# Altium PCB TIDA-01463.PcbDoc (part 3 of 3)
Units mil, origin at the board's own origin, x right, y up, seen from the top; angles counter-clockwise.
Board outline 6100 x 1060 mil, 4 copper layers (Top Layer, Signal Layer 1, Signal Layer 2, Bottom Layer), stack 61.2 mil thick; 209 components, 128 nets, 660 pads, 266 vias.
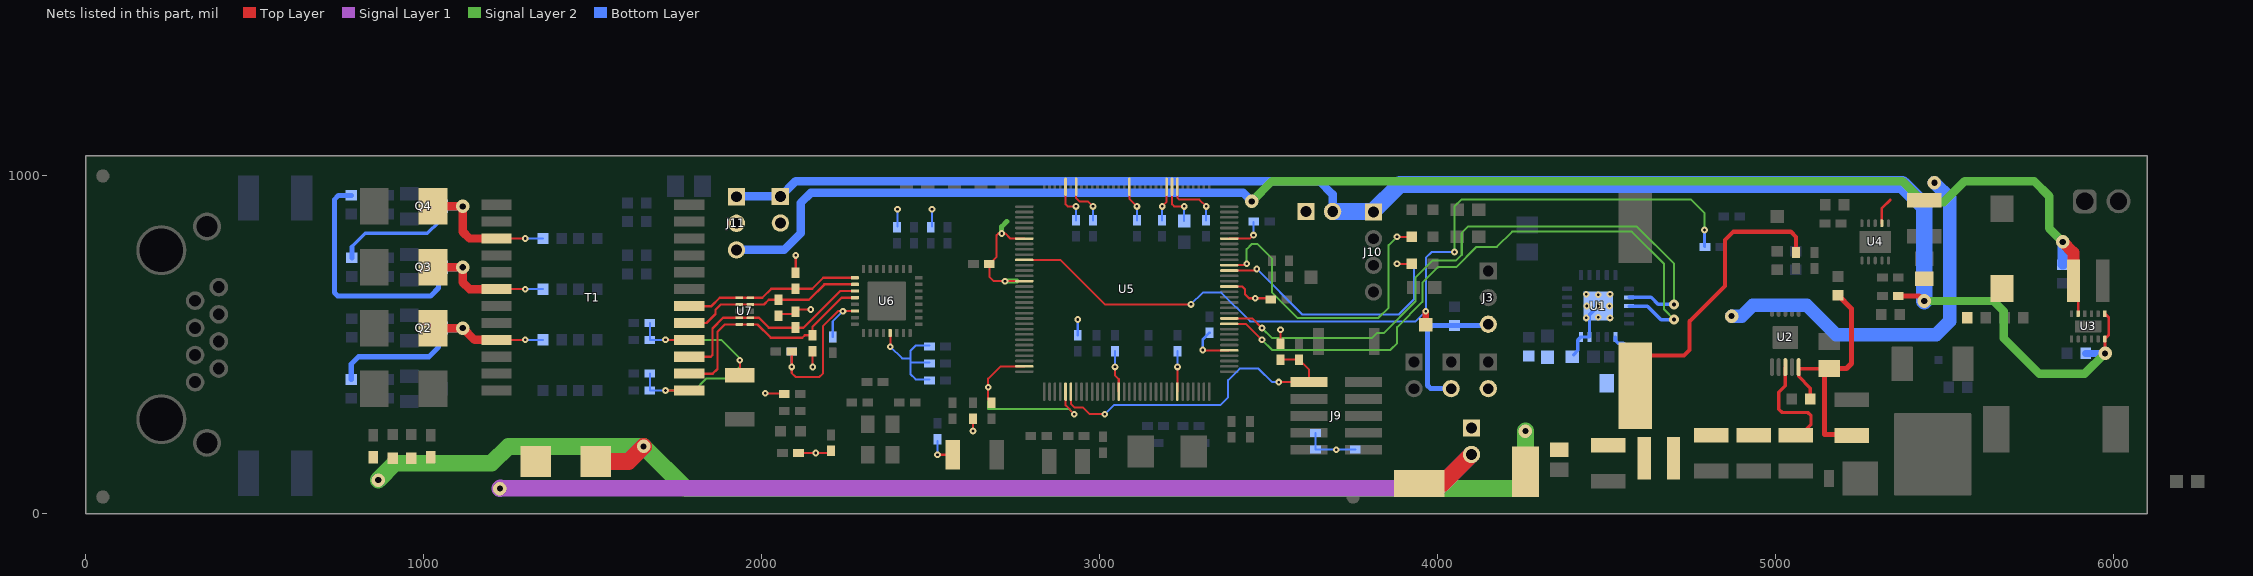
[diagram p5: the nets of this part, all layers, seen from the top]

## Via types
v1: diameter 20, hole 8, Top Layer to Bottom Layer, 184 vias
v2: diameter 40, hole 18, Top Layer to Bottom Layer, 50 vias
v3: diameter 19.68, hole 7.87, Top Layer to Bottom Layer, 21 vias
v4: diameter 30, hole 12, Top Layer to Bottom Layer, 11 vias

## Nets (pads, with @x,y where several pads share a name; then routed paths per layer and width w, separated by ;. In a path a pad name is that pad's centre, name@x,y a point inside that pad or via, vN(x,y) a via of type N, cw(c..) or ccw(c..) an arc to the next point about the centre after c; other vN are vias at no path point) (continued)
PR36: C7.1 D2.2 Q2.3 R9.2 T1.21 | length 793.1
  Top Layer w6: T1.21@1214.96,515 v1(1300,515)
  Top Layer w25: D2.2@1027.01,550 v2(1115,550) 1150,515 T1.21@1214.96,515
  Bottom Layer w6: v1(1300,515) C7.1@1352.44,515
  Bottom Layer w15: R9.2@785,397.56 785,443.35 806.65,465 1015,465 1043.31,493.31 Q2.3@1043.31,550
  Bottom Layer w25: Q2.3@1043.31,550 v2(1115,550)
PR45: C8.1 D3.2 Q3.3 R12.2 T1.18 | length 1164.4
  Top Layer w6: T1.18@1214.96,665 v1(1300,665)
  Top Layer w25: D3.2@1027.01,730 v2(1115,730) 1115,685 1135,665 T1.18@1214.96,665
  Bottom Layer w6: v1(1300,665) C8.1@1352.44,665
  Bottom Layer w15: R12.2@785,942.56 747.56,942.56 735,930 735,655 745,645 1020,645 1043.31,668.31 Q3.3@1043.31,730
  Bottom Layer w25: Q3.3@1043.31,730 v2(1115,730)
PR78: C9.1 D4.2 Q4.3 R11.2 T1.15 | length 845.6
  Top Layer w6: T1.15@1214.96,815 v1(1300,815)
  Top Layer w25: D4.2@1027.01,910 v2(1115,910) 1115,835 1135,815 T1.15@1214.96,815
  Bottom Layer w6: v1(1300,815) C9.1@1352.44,815
  Bottom Layer w10: 786.69,790.19 826.5,830 1010,830 1045,865 Q4.3@1045,908.31
  Bottom Layer w15: R11.2@786.69,757.56 786.69,790.19
  Bottom Layer w25: Q4.3@1043.31,910 v2(1115,910)
PWM_DIM: R69.1 TP5.1 U5.43 | length 2595
  Top Layer w6: U5.43@2776.85,751.61 2883.39,751.61 3015,620 v1(3270,620)
  Top Layer w20: TP5.1@3965,560 v1(3965,600)
  Signal Layer 2 w6: v1(4050,775) 4050,910 4070,930 4750,930 4790,890 v1(4790,840)
  Bottom Layer w6: v1(3270,620) 3305,655 3360,655 3445,570 3935,570 v1(3965,600) 3965,757.54 3982.46,775 v1(4050,775) ; R69.1@4790,791.38 R69.1@4791.38,790
  Bottom Layer w8: R69.1@4790,791.38 v1(4790,840)
RST_N: C54.1 J9.10 R47.1 R48.2 U5.70 | length 1051.8
  Top Layer w6: U5.70@2914.65,361.85 2914.65,325.35 2925,315 2950,315 2970,295 v1(3015,295) ; v1(3530,390) J9.10@3619.88,390 3619.88,426.5 R48.2@3590,456.38 R47.1@3535,456.38
  Bottom Layer w6: v1(3015,295) 3041.65,321.65 3356.65,321.65 3380,345 3380,395.91 3414.09,430 3470,430 3510,390 v1(3530,390) C54.1@3591.38,390
RXD_N: R55.1 T1.6 U6.9 U7.1 U7.10 | length 525.2
  Top Layer w7: T1.6@1785.04,615 1851,615 1875.37,639.37 U7.1@1933.56,639.37 U7.10@1966.44,639.37 2001.37,639.37 2028.38,666.38 R55.1@2100,666.38 2149.38,666.38 2181.9,698.9 U6.9@2275.51,698.9
RXD_P: R54.1 T1.5 U6.10 U7.2 U7.9 | length 545
  Top Layer w7: T1.5@1785.04,565 1836.4,565 1863,591.6 1863,604 1878.69,619.69 U7.2@1933.56,619.69 U7.9@1966.44,619.69 2006.69,619.69 2020.62,633.62 R54.1@2050,633.62 2139.62,633.62 2185.21,679.21 U6.10@2275.51,679.21
TPH: U1.18 U5.106 | length 1892
  Top Layer w6: U5.106@3383.15,562.64 3432.36,562.64 v1(3480,515)
  Signal Layer 2 w6: v1(3480,515) 3510,485 3860,485 3880,505 3880,552.7 3955,627.7 3955,684.57 4000.43,730 4055,730 4115,790 4175.29,790 4220.29,835 4575,835 4670,740 4670,605 v4(4700,575)
  Bottom Layer w10: U1.18@4566.54,615 4621.05,615 4661.05,575 v4(4700,575)
TPH_LED: D6.2 U5.116 | length 813.1
  Top Layer w6: U5.116@3383.15,720.12 3460.12,720.12 v1(3465,725) ; v1(3880,740) D6.2@3923.5,740
  Bottom Layer w6: v1(3465,725) 3600,590 3885,590 3930,635 3930,725 3915,740 v1(3880,740)
TPL: U1.17 U5.107 | length 1864.7
  Top Layer w6: U5.107@3383.15,578.39 3451.61,578.39 v1(3480,550)
  Signal Layer 2 w6: v1(3480,550) 3510,520 3805,520 3820,535 3840,535 3935,630 3935,700 3985,750 4055,750 4071.4,766.4 4071.4,831.91 4089.49,850 4590.01,850 4700,740.01 v4(4700,620)
  Bottom Layer w10: U1.17@4566.54,640.59 4631.51,640.59 4652.1,620 v4(4700,620)
TPL_LED: D7.2 U5.117 | length 948.7
  Top Layer w6: U5.117@3383.15,735.87 3430.87,735.87 v1(3435,740) ; v1(3880,820) D7.2@3923.5,820
  Signal Layer 2 w6: v1(3435,740) 3435,783.11 3450.75,798.86 3466.14,798.86 3510,755 3510,655 3585,580 3825,580 3855,610 3855,795 v1(3880,820)
TXD_N: R53.1 T1.3 U6.11 U7.4 U7.7 | length 641.6
  Top Layer w7: T1.3@1785.04,465 1849,465 1854,470 1854,549 1885.32,580.32 U7.4@1933.56,580.32 U7.7@1966.44,580.32 1991.68,580.32 2021,551 2123.57,551 2232.1,659.53 U6.11@2275.51,659.53
TXD_P: R52.1 T1.2 U6.12 U7.5 U7.6 | length 695.7
  Top Layer w7: T1.2@1785.04,415 1855,415 1869,429 1869,539 1890.63,560.63 U7.5@1933.56,560.63 U7.6@1966.44,560.63 1987.37,560.63 2027,521 2120,521 2127.62,528.62 R52.1@2150,528.62 2150,554 2235.84,639.84 U6.12@2275.51,639.84
VCC_1P8: C29.1 J11.3 L5.2 U3.5 | length 4564.1
  Top Layer w8: L5.2@5881.69,690 5895.47,676.22 U3.5@5895.47,592.4
  Top Layer w35: v2(5850,805) 5881.69,773.31 L5.2@5881.69,690
  Signal Layer 2 w25: v2(3450,925) 3510,985 5375,985 5437.76,922.24 5497.24,922.24 5560,985 5765,985 5810,940 5810,845 v2(5850,805)
  Bottom Layer w25: J11.3@1925,781.26 2066.26,781.26 2115,830 2115,920 2145.5,950.5 3395,950 3425,950 v2(3450,925)
  Bottom Layer w30: C29.1@5850,737.56 v2(5850,805)
VCC_3P3: C57.1 C58.1 C59.1 C60.1 J12.2 R57.1 R58.2 R60.2 R61.2 R64.1 R65.2 R66.2 U6.21 | length 770.9
  Top Layer w6: v1(2010,356.81) R66.2@2066.38,356.81 ; R64.1@2108.62,180 v1(2160,180) 2198.62,180 R58.2@2205,186.38 ; v1@2380.32,495.12 U6.21@2380.32,540.47 ; v1(2520,175) C57.1@2565.04,175 C57.1@2565.04,175 C57.1@2565.04,155 ; v1(2625,245) R61.2@2625,281.38
  Bottom Layer w6: v1(2380.47,494.96) 2415.43,460 2440,460 ; R60.2@2401.81,850.43 v1(2401.81,901.81) ; C59.1@2496.38,398.35 2455,398.35 2440,413.35 2440,448.35 ; C60.1@2496.38,448.35 2440,448.35 ; C58.1@2496.38,498.35 2455,498.35 2440,483.35 2440,460 ; R65.2@2503.62,850.43 v1(2503.62,901.81) ; v1(2520,175) R57.1@2520,215.47 ; 2440,448.35 2440,460
VCC_3P3_EXT: C27.1 C28.1 C30.1 J8.2 J10.1 J11.1 J12.1 L6.2 R34.2 U3.1 U3.12 | length 4903.6
  Top Layer w8: U3.1@5974.21,592.4 5986.02,580.59 5986.02,529.41 U3.12@5974.21,517.6 5975,516.81 v2(5975,475)
  Top Layer w15: R34.2@5363.62,645 5425,645 v2(5440,630)
  Signal Layer 2 w25: v2(5440,630) 5645,630 5675,600 5675,520 5780,415 5915,415 v2(5975,475)
  Bottom Layer w20: C28.1@5917.56,475 v2(5975,475)
  Bottom Layer w25: J11.1@1925.63,939.37 J12.1@2055,939.37 2100.63,985 3650,985 3689.37,945.63 J8.2@3689.37,895
  Bottom Layer w50: J8.2@3689.37,895 3808.11,895 3888.11,975 5375,975 5440,910 v2(5440,630)
VCC_3P3_M: C34.1 C35.1 C36.1 C37.1 C38.1 C39.1 C40.1 C41.1 C42.1 C43.1 C44.1 C45.1 C46.1 J8.1 R41.2 R42.2 R43.2 R46.1 R47.2 U5.7 U5.8 U5.9 U5.16 U5.26 U5.28 U5.39 U5.47 U5.63 U5.69 U5.79 U5.90 U5.101 U5.113 U5.122 | length 2689.3
  Top Layer w6: C43.1@2680,328.62 2670,338.62 v1(2670,375) 2670,400 2706.65,436.65 U5.63@2776.85,436.65 ; U5.47@2776.85,688.62 v1(2720,688.62) 2686.38,688.62 2673.62,701.38 C44.1@2673.62,740 2695,761.38 2695,825 2700,830 v1(2710,830) 2720,830 2735,815 2776.46,815 U5.39@2776.85,814.61 ; U5.69@2898.9,361.85 2898.9,321.1 v1(2925,295) ; U5.28@2898.9,968.15 2898.9,916.1 2905,910 v1(2930,910) ; U5.26@2930.39,968.15 2930.39,934.61 2940,925 2965,925 v1(2980,910) ; v1(3045,435) 3045,410 3056.38,398.62 U5.79@3056.38,361.85 ; U5.16@3087.87,968.15 3087.87,932.13 v1(3110,910) ; v1(3185,910) 3198.11,923.11 U5.9@3198.11,968.15 ; U5.8@3213.86,968.15 3213.86,916.14 3220,910 v1(3250,910) ; U5.90@3229.61,361.85 3229.61,434.61 v1(3230,435) ; U5.7@3229.61,968.15 3229.61,935.39 3235,930 3295,930 v1(3315,910) ; v1(3305,485) 3306.1,483.9 U5.101@3383.15,483.9 ; U5.113@3383.15,672.87 3422.13,672.87 3430,665 3430,650 3441.85,638.15 v1(3460,638.15) C42.1@3508.23,638.15 ; U5.122@3383.15,814.61 3444.61,814.61 v1(3455,825) ; R47.2@3535,503.63 v1(3535,545)
  Signal Layer 2 w6: v1(2670,375) 2670,310 2910,310 v1(2925,295)
  Signal Layer 2 w15: v1(2710,830) 2710,850 2725,865 ; v1(2720,688.62) 2755,688.62
  Bottom Layer w6: C38.1@2930,868.62 v1(2930,910) ; R46.1@2935,528.62 v1(2935,575) ; C37.1@2980,868.62 v1(2980,910) ; v1(3045,435) C39.1@3045,481.38 ; C36.1@3110,868.62 v1(3110,910) ; C34.1@3185,868.62 v1(3185,910) ; v1(3230,435) C40.1@3230,481.38 ; C35.1@3250,866.5 v1(3250,910) ; C46.1@3315,868.62 v1(3315,910) ; v1(3455,825) C45.1@3455,863.62 ; R42.2@3638.62,240 R41.2@3638.62,190 v1(3700,190) R43.2@3756.38,190
  Bottom Layer w8: v1(3305,485) 3305,516.38 C41.1@3325,536.38
VCC_SW: C1.1 C2.1 C3.1 C4.1 C61.1 C62.1 C63.1 C64.1 J11.2 R52.2 R53.2 R54.2 R55.2 T1.1 T1.4 U6.14 | length 1625.2
  Top Layer w6: v1@1710,365 T1.1@1785.04,365 ; v1(1715,515) T1.4@1785.04,515 ; C61.1@1935,409.96 v1(1935,455) ; R54.2@2050.47,591.34 2089.45,591.34 2103.11,605 v1(2145,605) ; C64.1@2088.62,481.81 v1(2088.62,435) 2088.62,416.38 2100,405 2170.51,405 2180.47,414.96 2180.47,554.96 2225.51,600 v1(2240,600) 2240.47,600.47 U6.14@2275.51,600.47 ; R55.2@2100.47,718.58 v1(2100.47,764.96) ; v1(2150.47,434.96) R52.2@2150.47,485.12
  Signal Layer 2 w6: v1(1715,365) 1800,365 1835,400 1900,400 1935,435 ; v1(1715,515) 1880,515 v1@1935,460
  Bottom Layer w6: C1.1@1668.62,415 C2.1@1668.62,365 v1(1715,365) ; C3.1@1668.62,565 C4.1@1668.62,515 v1(1715,515) ; v1(2088.62,435) C62.1@2088.62,480 ; C63.1@2210,523.62 2210,570 v1(2240,600)
VDD: C12.1 C17.1 C18.1 C19.1 C24.1 D5.1 L1.2 L3.1 R21.2 R22.2 TP1.1 U1.1 | length 4795.4
  Top Layer w12: C17.1@4585,378.94 4585,460 4593.53,468.53 4728.53,468.53 4745,485 4745,570 4850,675 4850,810 4875,835 5045,835 5060,820 R22.2@5060,777.56
  Top Layer w50: D5.1@1507.01,155 1605,155 v2(1650,200)
  Signal Layer 2 w50: v2(865,100) 915,150 1200,150 1250,200 v2(1650,200) 1775,75 4260,75 v2(4260,245)
  Bottom Layer w10: U1.1@4526.18,523.46 4526.18,513.82 4535,505 4550,505 4562.56,492.44 R21.2@4562.56,465
  Bottom Layer w12: C24.1@4559.53,386.42 C24.1@4562.56,389.45
VDD_P: C20.1 C21.1 C22.1 C23.1 C25.1 C31.1 L3.2 R23.2 R33.2 U2.8 U2.10 U4.2 | length 2318.8
  Top Layer w8: U4.2@5314.69,860.12 5314.69,904.69 5339.61,929.61 ; C31.1@5423.15,945 C31.1@5440,928.15
  Top Layer w10: U2.8@5028.98,434.29 5028.98,378.98 5010,360 5010,310 5020,300 5095,300 5105,290 5105,265 C22.1@5073.15,233.15 ; C25.1@5102.56,340 5102.56,372.44 5068.35,406.65 5068.35,434.29 5072.64,430 C23.1@5158.98,430 C23.1@5148.98,420
  Top Layer w15: C23.1@5148.98,420 5145,416.02 5145,235 R23.2@5221.85,235 ; C23.1@5158.98,430 5210,430 5225,445 5225,607.44 R33.2@5185,647.44
  Bottom Layer w40: v2(4870,585) 4900,585 4932.54,617.54 5092.46,617.54 5180,530 5475,530 5515,570 5515,935 v2(5470,980)
VSS: C24.2 J2.2 J3.3 J5.1 J6.2 R17.2 R29.1 R30.1 R31.2 U1.4 U1.5 U1.21@4475,615 | length 609.1
  Bottom Layer w10: R29.1@4402.44,471.14 4415,483.7 4415,514.65 U1.5@4423.82,523.46 U1.4@4449.41,523.46 4449.41,589.41 v3(4475,615)
  Bottom Layer w15: J6.2@4040,370.63 3979.37,370.63 3970,380 3970,545 3982.44,557.44 R17.2@4050,557.44 J3.3@4146.18,557.44
  other v1: 4440,580 4510,580 4440,650 4510,650
  other v3: 4475,581.54 4441.54,615 4508.46,615 4475,648.46
VSS1: C12.2 D5.2 J5.2 L2.2 TP2.1 | length 3107.8
  Top Layer w50: TP2.1@3945,90 4014.37,90 J5.2@4100,175.63
  Signal Layer 1 w50: v2(1225,75) 1226.5,76.5 3955,75 3999.37,75 J5.2@4100,175.63
pads on no net: FID1.1 FID2.1 FID3.1 J9.7 R?.1 R?.2 SH-J1.0 SH-J2.0 SH-J3.0 SH-J4.0 SH-J5.0 SH-J6.0 SH-J7.0 SH-J8.0 T1.7 T1.10 U1.14 U1.15 U1.20 U1.21@4451.77,591.77 U1.21@4451.77,638.23 U1.21@4498.23,591.77 U1.21@4498.23,638.23 U3.6 U3.7 U3.13@5903.35,555 U3.13@5946.65,555 U4.6 U5.1 U5.2 U5.3 U5.4 U5.5 U5.6 U5.11 U5.12 U5.13 U5.14 U5.15 U5.18 U5.19 U5.20 U5.21 U5.22 U5.23 U5.24 U5.25 U5.27 U5.29 U5.30 U5.31 U5.32 U5.33 U5.34 U5.35 U5.36 U5.37 U5.38 U5.41 U5.46 U5.49 U5.50 U5.65 U5.73 U5.74 U5.75 U5.76 U5.77 U5.78 U5.81 U5.82 U5.83 U5.84 U5.85 U5.86 U5.91 U5.92 U5.93 U5.94 U5.102 U5.103 U5.104 U5.108 U5.109 U5.110 U5.111 U5.112 U5.123 U5.124 U5.125 U5.126 U5.127 U5.128 U6.13 U6.15 U6.33@2341.06,601.06 U6.33@2341.06,658.94 U6.33@2398.94,601.06 U6.33@2398.94,658.94 U7.3@1933.56,600 U7.8@1966.44,600

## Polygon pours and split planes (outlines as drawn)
NetJ7_1 on Top Layer "TOP_LAYER_NONET_P020" (solid, remove dead copper, shelved, pour order 20): 6050,50 6050,460 5955,460 5830,460 5830,50
NetD10_1 on Top Layer "TOP_LAYER_NONET_P018" (solid, remove dead copper, shelved, pour order 18): 5195,50 5790,50 5790,460 5615,460 5615,350 5565,300 5350,300 5350,170 5195,170
VDD on Top Layer "TOP_LAYER_NONET_P016" (solid, remove dead copper, shelved, pour order 16): 4305,50 4305,165 4580,165 4580,100 4635,100 4635,520 4400,520 4215,520 4215,335 4215,50
VDD_P on Top Layer "TOP_LAYER_NONET_P014" (solid, remove dead copper, shelved, pour order 14): 4670,100 4725,100 4725,200 5285,200 5285,270 4830,270 4830,350 4915,435 4915,575 4915,610 4785,610 4785,575 4785,490 4730,435 4670,435 4670,270
VDD on Top Layer "TOP_LAYER_NONET_P004" (solid, remove dead copper, shelved, pour order 4): 925,190 800,190 800,50 925,50
VSS1 on Top Layer "TOP_LAYER_NONET_P002" (solid, remove dead copper, shelved, pour order 2): 945,190 945,50 1400,50 1400,235 1250,235 1245,235 1200,190
BR+ on Top Layer "TOP_LAYER_NONET_P000" (solid, remove dead copper, shelved, pour order 0): 925,210 925,985 805,985 800,980 800,210
BSVG on Top Layer "TOP_LAYER_NONET_P060" (solid, remove dead copper, shelved, pour order 60): 515,50 50,50 50,1000 515,1000 515,865 450,865 385,800 350,800 250,700 150,700 150,365 255,365 365,255 390,255 455,190 515,190
VSS on Top Layer "TOP_LAYER_NONET_P048" (solid, remove dead copper, shelved, pour order 48): 4415,545 4415,675 4535,675 4535,545
GND on Top Layer "TOP_LAYER_NONET_P054" (solid, remove dead copper, shelved, pour order 54): 4330,50 4330,150 4555,150 4555,95 4670,95 4670,544.9 4669.9,545 4550,545 4550,690 4540,700 4200,700 4200,765 4025,765 4025,575 3955,575 3955,235 3835,115 1850,115 1850,1000 6050,1000 6050,50
BR- on Top Layer "TOP_LAYER_NONET_P032" (solid, remove dead copper, shelved, pour order 32): 945,210 1115,210 1115,260 945,260
VDD_P on Top Layer "TOP_LAYER_NONET_P034" (solid, remove dead copper, shelved, pour order 34): 5495,910 5495,905 5305,905 5305,1000 5495,1000
NetQ5_3 on Top Layer "TOP_LAYER_NONET_P042" (solid, remove dead copper, shelved, pour order 42): 5170,315 5305,315 5305,345 5340,380 5410,380 5410,500 5255,500 5255,380 5238.74,363.74 5169.88,363.74
VCC_3P3_EXT on Top Layer "TOP_LAYER_NONET_P038" (solid, remove dead copper, shelved, pour order 38): 5410,560 5585,560 5585,625 5819.61,625 5819.61,720 5819.61,780 5515,780 5515,720 5410,720
NetL6_1 on Top Layer "TOP_LAYER_NONET_P040" (solid, remove dead copper, shelved, pour order 40): 5820,820 5515,820 5515,1000 5820,1000
VDD on Bottom Layer "BOTTOM_LAYER_NONET_P064" (solid, shelved, pour order 64): 4215,50 4215,250 4250,285 4540,285 4540,485 4635,485 4635,175 4305,175 4305,50
VSS on Bottom Layer "BOTTOM_LAYER_NONET_P050" (solid, remove dead copper, shelved, pour order 50): 4530,560 4530,670 4420,670 4420,560
no net on Bottom Layer "BOTTOM_LAYER_NONET_P024" (solid, remove dead copper, shelved, pour order 24): 4400,810 4210,810 4210,925 4400,925
BSVG on Bottom Layer "BOTTOM_LAYER_NONET_P062" (solid, remove dead copper, shelved, pour order 62): 515,50 50,50 50,1000 515,1000 515,865 450,865 385,800 350,800 250,700 150,700 150,365 255,365 360,260 365,255 390,255 455,190 515,190
VSS on Bottom Layer "BOTTOM_LAYER_NONET_P006" (solid, remove dead copper, shelved, pour order 6): 4150,225 4235,310 4515,310 4515,420 4420,420 4420,485 4225,485 4225,420 4215,410 4205,400 4000,400 4000,225
GND on Bottom Layer "BOTTOM_LAYER_NONET_P056" (solid, remove dead copper, shelved, pour order 56): 4330,50 4330,150 4555,150 4555,95 4670,95 4670,545 4550,545 4550,690 4540,700 4200,700 4200,765 4025,765 4025,575 3955,575 3955,235 3835,115 1850,115 1850,1000 6050,1000 6050,50
VDD on Signal Layer 2 "SIGNAL_LAYER_2_NONET_P066" (solid, shelved, pour order 66): 4215,50 4215,250 4250,285 4560,285 4560,520 4635,520 4635,175 4305,175 4305,50
VCC_3P3 on Signal Layer 2 "SIGNAL_LAYER_2_NONET_P030" (solid, remove dead copper, shelved, pour order 30): 2020,890 2020,810 2280,810 2280,370 1850,370 1850,120 2640,120 2640,890 2640,935 2110,935 2110,890
VCC_SW on Signal Layer 2 "SIGNAL_LAYER_2_NONET_P028" (solid, remove dead copper, shelved, pour order 28): 2000,890 1850,890 1850,385 2260,385 2260,790 2000,790
VCC_3P3_M on Signal Layer 2 "SIGNAL_LAYER_2_NONET_P026" (solid, remove dead copper, shelved, pour order 26): 3835,115 2655,115 2655,1000 3645,1000 3645,405 3835,405
VSS on Signal Layer 2 "SIGNAL_LAYER_2_NONET_P044" (solid, remove dead copper, shelved, pour order 44): 4415,675 4415,485 4225,485 4225,420 4215,410 4205,400 4000,400 4000,310 4000,225 4150,225 4235,310 4415,310 4535,310 4535,675
GND on Signal Layer 2 "SIGNAL_LAYER_2_NONET_P058" (solid, remove dead copper, shelved, pour order 58): 4330,50 6050,50 6050,1000 4000,1000 4000,700 4555,700 4555,545 4670,545 4670,95 4555,95 4555,150 4330,150
VDD on Signal Layer 1 "SIGNAL_LAYER_1_NONET_P068" (solid, shelved, pour order 68): 4215,50 4215,250 4250,285 4560,285 4560,520 4635,520 4635,175 4630,180 4305,180 4305,50
GND on Signal Layer 1 "SIGNAL_LAYER_1_NONET_P052" (solid, remove dead copper, shelved, pour order 52): 4330,50 4330,150 4555,150 4555,95 4670,95 4670,545 4550,545 4550,690 4540,700 4200,700 4200,765 4025,765 4025,575 3955,575 3955,235 3835,115 3105,115 1850,115 1850,1000 6050,1000 6050,50 4610,50
VSS on Signal Layer 1 "SIGNAL_LAYER_1_NONET_P046" (solid, remove dead copper, shelved, pour order 46): 4415,310 4235,310 4150,225 4000,225 4000,400 4205,400 4225,420 4225,485 4415,485 4415,675 4535,675 4535,310

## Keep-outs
Keep-Out Layer:
  lines w8: 6100,1064 0,1064 ; 6104,1060 6104,0 ; -4,0 ccw(c0,0) 0,-4 ; -4,0 ccw(c0,0) 0,-4 ; -4,0 -4,1060 ; -4,1060 cw(c0,1060) 0,1064 ; -4,1060 cw(c0,1060) 0,1064 ; 0,-4 6100,-4 ; 6100,-4 ccw(c6100,0) 6104,0 ; 6100,-4 ccw(c6100,0) 6104,0

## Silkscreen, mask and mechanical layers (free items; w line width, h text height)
Top Overlay:
  lines w8: 2210,565 2210.77,565.77 2210.77,607.83 ; 2300,425 2300,460 ; 2795,170 2795,195 ; 2883.15,286.85 2898.15,286.85 2920,265 ; 4700,70 4725,70 4750,95 ; 5185,620 5200,605 5210,605 5220,595 5220,540 5230,530 5245,530 ; 5260,665 5280,685 ; 5400,620 5415,605
Bottom Overlay:
  text "'.PRJ_Number'.PCB_Rev" at 3330,45 h108.27
M1 Board Outline:
  the board outline again, w10
M2 Board Dimensions:
  rectangle: 0,-275 125,-150
  rectangle: 125,-400 500,-275
  lines w7: 0,-275 1000,-275 ; 125,-400 125,-150 ; 250,-400 250,-150 ; 500,-400 500,-150 ; 750,-400 750,-150 ; 0,-400 1000,-400 1000,-150 0,-150 0,-400
M5 Assembly Top:
  lines w10: -292,-930.17 6308,-930.17 ; -292,-726.83 6310,-726.83 ; -292,-523.5 -292,-1133.5 3713,-1133.5 6310,-1133.5 6310,-523.5 -291.5,-523.5 -291.5,-1133.5 1284,-1133.5 ; 2173,-1133.5 2173,-523.5 ; 3440,-726.83 3440,-523.5 ; 4280,-726.83 4280,-523.5 ; 4902,-1140 4902,-937.17
  text "COMPONENTS MARKED 'DNP' SHOULD NOT BE POPULATED." at 1153.5,-318.5 h60
  text "ASSEMBLY VARIANT:" at 1153,-434 h60
  text ".VariantName" at 2189,-434 h60
  text "PCB VIEWED FROM TOP SIDE" at -228.5,-655.67 h60
  text "BOARD #:" at 2248,-655.67 h60
  text ".PRJ_Number" at 2793.5,-655.67 h60
  text "REV:" at 3638,-655.67 h60
  text ".PCB_Rev" at 3929.5,-655.67 h60
  text "SVN REV:" at 4476,-655.67 h60
  text ".VersionControl_RevNumber" at 4982,-655.67 h60
  text "TID #:" at 2248,-859 h60
  text ".TID" at 2793.5,-859 h60
  text "PLOT NAME =" at -228.5,-1064.34 h60
  text ".plot_File_Name" at 577,-1064.34 h60
  text "GENERATED    :" at 2250,-1064.34 h60
  text ".Print_Date" at 3119.5,-1064.34 h60
  text ".Print_Time" at 3848.5,-1064.34 h60
  text "TEXAS INSTRUMENTS" at 5113,-1064.34 h60
M6 Assembly Bottom:
  lines w10: -292.5,-727.33 6309.5,-727.33 ; -290.5,-930.67 6309.5,-930.67 ; 1115.5,-1140.5 1115.5,-937.67 ; 1737.5,-727.33 1737.5,-524 ; 2577.5,-727.33 2577.5,-524 ; 3844.5,-1134 3844.5,-524 ; 4733.5,-1134 6309,-1134 6309,-524 -292.5,-524 -292.5,-1134 2304.5,-1134 6309.5,-1134 6309.5,-524
  text "COMPONENTS MARKED 'DNP' SHOULD NOT BE POPULATED." at 6102,-318 h60
  text ".VariantName" at 5058,-434 h60
  text "ASSEMBLY VARIANT:" at 6097,-434 h60
  text ".VersionControl_RevNumber" at 1035.5,-656.17 h60
  text "SVN REV:" at 1541.5,-656.17 h60
  text ".PCB_Rev" at 2088,-656.17 h60
  text "REV:" at 2379.5,-656.17 h60
  text ".PRJ_Number" at 3224,-656.17 h60
  text "BOARD #:" at 3769.5,-656.17 h60
  text "PCB VIEWED FROM BOTTOM SIDE" at 6246,-656.17 h60
  text ".TID" at 3224,-859.5 h60
  text "TID #:" at 3769.5,-859.5 h60
  text "TEXAS INSTRUMENTS" at 904.5,-1064.84 h60
  text ".Print_Time" at 2169,-1064.84 h60
  text ".Print_Date" at 2898,-1064.84 h60
  text "GENERATED    :" at 3767.5,-1064.84 h60
  text ".plot_File_Name" at 5440.5,-1064.84 h60
  text "PLOT NAME =" at 6246,-1064.84 h60
M9 Title Sheet:
  drawing of 56 lines, arcs and shapes, not listed
  text "1" at 739.84,8036.5 h70
  text "2" at 3235.5,8036.5 h70
  text "3" at 5724.84,8036.5 h70
  text "4" at 8231.51,8036.5 h70
  text "5" at 10730.5,8036.5 h70
  text "6" at 13235.5,8036.5 h70
  text "A" at -416.5,6893.5 h70
  text "A" at 14383.5,6893.5 h70
  text "B" at -416.5,4513.5 h70
  text "B" at 14383.5,4513.5 h70
  text "C" at -416.5,2138.5 h70
  text "C" at 14383.5,2138.5 h70
  text "PROJECT TITLE:" at 11343.5,277.5 h45
  text ".PRJ_Title" at 11393.5,144.17 h70
  text "DESIGNED FOR:" at 11343.5,-23.5 h45
  text ".PRJ_Customer" at 11393.5,-163.5 h70
  text "D" at -416.5,-231.5 h70
  text "D" at 14383.5,-231.5 h70
  text "FILE NAME:" at 11343.5,-323.5 h45
  text ".PCB_File_Name_No_Path" at 11393.5,-443.5 h70
  text "Texas Instruments (TI) and/or its licensors do not warrant the accuracy or completeness of this specification" at 6374,-605.34 h45
  text "ENGINEER:" at 11343.5,-613.5 h45
  text "LAYOUT BY:" at 12848.5,-613.5 h45
  text "or any information contained therein. TI and/or its licensors do not warrant that this design will meet" at 6329.01,-718 h45
  text ".PRJ_Engineer" at 11393.5,-768.49 h70
  text ".PCB_Layout" at 12899,-768.49 h70
  text "the specifications, will be suitable for your application or fit for any particular purpose, or will operate in" at 6329.01,-830.67 h45
  text "ALTIUM DESIGNER VERSION:" at 12848.5,-923.5 h45
  text "an implementation. TI and/or its licensors do not warrant that the design is production worthy. You should" at 6329.01,-943.33 h45
  text "completely validate and test your design implementation to confirm the system functionality for your application." at 6374,-1056 h45
  text ".print_Scale" at 11393.5,-1056.83 h70
  text ".Application_BuildNumber" at 12899,-1056.83 h70
  text "1" at 739.84,-1263.5 h70
  text "2" at 3235.5,-1263.5 h70
  text "3" at 5724.84,-1263.5 h70
  text "4" at 8231.51,-1263.5 h70
  text "5" at 10730.5,-1263.5 h70
  text "6" at 13235.5,-1263.5 h70
M10 Fab Notes:
  drawing of 173 lines, arcs and shapes, not listed
  text "DESIGN INFORMATION" at 12378.02,6201 h60
  text "MIN. TRACK WIDTH:" at 11733.46,6021 h60
  text "8" at 12829.7,6021 h60
  text "MIL" at 12984.46,6021 h60
  text "MIN. CLEARANCE:" at 11733.46,5889 h60
  text "0.2" at 12769.7,5889 h60
  text "mm" at 12984.46,5889 h60
  text "MIN. VIA PAD SIZE:" at 11733.46,5757 h60
  text "24" at 12799.71,5757 h60
  text "MIL" at 12984.46,5757 h60
  text "0.05mm (2MIL)" at 12428.46,5615.29 h60
  text "MINIMUM ANNULAR RING" at 11404.23,5611 h60
  text "EXTERNAL" at 13136.46,5611 h60
  text "PER" at 11604.23,5493 h60
  text "IPC-D-275 CLASS 2 LEVEL C" at 11824.23,5493 h60
  text "MIL, HOLES" at 13312.46,5380.71 h60
  text "+/-" at 12920,5380 h60
  text "+/-" at 13774,5380 h60
  text "REGISTRATION TOLERANCES:" at 11404.23,5375 h60
  text "METAL" at 12604,5375 h60
  text "5" at 13180.2,5375 h60
  text "3" at 14013.2,5375 h60
  text "MIL" at 14129.46,5375 h60
  text "+/-" at 13774,5262 h60
  text "HOLE SIZE TOLERANCE (UNLESS OTHERWISE SPECIFIED):" at 11404.23,5257 h60
  text "3" at 14013.2,5257 h60
  text "MIL" at 14129.46,5257 h60
  text "MATERIAL:" at 11329.46,5047.54 h60
  text "FR-4 High Tg" at 12315.9,4907.21 h60
  text "FR-408" at 11750.46,4898.64 h60
  text "OTHER" at 13238.46,4898.64 h60
  text "X" at 12161,4895 h60
  text "62 MIL (1.6mm) +/-10%" at 12070.56,4735.92 h60
  text "THICKNESS:" at 11404.23,4731.64 h60
  text "X" at 11942.4,4731.64 h60
  text "OTHER" at 13355.46,4731.64 h60
  text "TOLERANCE:" at 11404.23,4573.64 h60
  text "X" at 12243.53,4573.64 h60
  text "ANSI IPC-6012 TYPE 3 CLASS 2" at 12430.48,4573.64 h60
  text "OTHER +/-" at 12430.46,4417.64 h60
  text "BOW & TWIST:" at 11404.23,4260.64 h60
  text "X" at 12243.53,4260.64 h60
  text "ANSI IPC-6012 TYPE 3 CLASS 2" at 12430.48,4260.64 h60
  text "OTHER +/-" at 12430.46,4102.13 h60
  text "DRILLING:" at 11329.46,3963.64 h60
  text "REFERENCE:" at 11404.23,3846.64 h60
  text "X" at 12052.46,3846.64 h60
  text "AS SHOWN" at 12239.46,3846.64 h60
  text "X" at 12953.46,3846.64 h60
  text "NC_DRILL FILES" at 13090.46,3846.64 h60
  text "PTH COPPER THICKNESS:" at 11404.23,3688.64 h60
  text "X" at 12534.46,3688.64 h60
  text "20-30 um" at 12671.46,3688.64 h60
  text "OTHER" at 13388.46,3688.64 h60
  text "BOARD FINISH:" at 11329.46,3529.64 h60
  text "SILKSCREEN:" at 11484.68,3411.64 h60
  text "X" at 12433.46,3411.64 h60
  text "TOP" at 12559.46,3411.64 h60
  text "X" at 12943.46,3411.64 h60
  text "BOTTOM" at 13070.46,3411.64 h60
  text "SILKSCREEN COLOR:" at 11484.68,3244.64 h60
  text "X" at 12432.42,3244.64 h60
  text "WHITE" at 12559.46,3244.64 h60
  text "OTHER" at 13070.46,3244.64 h60
  text "X" at 12563.42,3085.44 h60
  text "GREEN" at 12690.46,3085.44 h60
  text "OTHER" at 13308.46,3085.44 h60
  text "SOLDER RESIST COLOR:" at 11484.68,3074.64 h60
  text "MATTE" at 12690.46,2915.44 h60
  text "SEMI-GLOSS" at 13308,2914.8 h60
  text "IMMERSION GOLD (ENIG)" at 12390.46,2726.92 h60
  text "ENEPIG" at 13728,2723.64 h60
  text "SURFACE FINISH:" at 11329.46,2722.64 h60
  text "X" at 12203.51,2722.64 h60
  text "IMM. TIN/SILVER OR EQUIV" at 11659,2565.64 h60
  text "OTHER" at 13090.46,2565.64 h60
  text "ARRAY/PANEL:" at 11329.46,2386.64 h60
  text "X" at 12205,2385 h60
  text "CUT AND TRIM PER M1 BOARD OUTLINE" at 12390.46,2382.35 h60
  text "N.C. ROUTE" at 12390.46,2230.64 h60
  text "V. SCORE" at 13256.46,2230.64 h60
  text "CERTIFICATION:" at 11329.46,2093.64 h60
  text "MATERIALS AND WORKMANSHIP FOR ALL PCBS" at 12054.46,2093.64 h60
  text "TO MEET OR EXCEED THE REQUIREMENTS OF:" at 12054.46,1995.64 h60
  text "X" at 11680.96,1859.13 h60
  text "ANSI IPC-A-600F CLASS ->" at 11819.96,1859.13 h60
  text "X" at 13459.02,1859.13 h60
  text "2" at 13577.96,1859.14 h60
  text "1" at 13262.96,1857.64 h60
  text "3" at 13931.96,1857.64 h60
  text "X" at 12495.02,1699.64 h60
  text "RoHS" at 12631.96,1699.64 h60
  text "OTHER" at 13276.36,1699.64 h60
  text "PER ORDER" at 13673.42,1699.64 h60
  text "ALL BOARDS MUST MEET OR EXCEED UL94-V0 REQUIREMENTS." at 11357,1534 h60
  text "PCB MUST BEAR THE UL94V-0 UL REGISTERED MATERIAL ID NUMBER" at 11357,1414 h60
  text "ADDITIONAL REQUIREMENTS:" at 11329.46,1240.64 h60
  text "MICROSECTION:" at 11404.23,1125.64 h60
  text "YES" at 12309.96,1125.64 h60
  text "REQUIRED" at 13171.46,969.49 h60
  text "BARE BOARD ELEC. TEST:" at 11404.23,966.64 h60
  text "NONE" at 12709.96,966.64 h60
  text "X" at 13044.46,966.64 h60
  text "PER ORDER" at 13763.46,966.64 h60
M11 Gerber Information:
  lines w10: -292,-930.17 6308,-930.17 ; -292,-726.83 6310,-726.83 ; -292,-523.5 -292,-1133.5 3713,-1133.5 6310,-1133.5 6310,-523.5 -291.5,-523.5 -291.5,-1133.5 1284,-1133.5 ; 2173,-1133.5 2173,-523.5 ; 3440,-726.83 3440,-523.5 ; 4280,-726.83 4280,-523.5 ; 4902,-1140 4902,-937.17
  text "ALL ARTWORK VIEWED FROM TOP SIDE" at -228.5,-655.67 h60
  text "BOARD #:" at 2248,-655.67 h60
  text ".PRJ_Number" at 2793.5,-655.67 h60
  text "REV:" at 3638,-655.67 h60
  text ".PCB_Rev" at 3929.5,-655.67 h60
  text "SVN REV:" at 4476,-655.67 h60
  text ".VersionControl_RevNumber" at 4982,-655.67 h60
  text "LAYER NAME =" at -228.5,-858.49 h60
  text "TID #:" at 2248,-859 h60
  text ".TID" at 2793.5,-859 h60
  text "PLOT NAME =" at -228.5,-1064.34 h60
  text ".plot_File_Name" at 577,-1064.34 h60
  text "GENERATED    :" at 2250,-1064.34 h60
  text ".Print_Date" at 3119.5,-1064.34 h60
  text ".Print_Time" at 3848.5,-1064.34 h60
  text "TEXAS INSTRUMENTS" at 5113,-1064.34 h60
M12 Stackup:
  drawing of 295 lines, arcs and shapes, not listed
  text "Layer" at 9750.88,7789.68 h60
  text "Name" at 10160.8,7789.68 h60
  text "Material" at 11100.54,7789.68 h60
  text "Thickness" at 11960.3,7789.68 h60
  text "Constant" at 12610.14,7789.68 h60
  text "Board Layer Stack" at 13180,7789.68 h60
  text "1" at 9750.88,7669.68 h60
  text "Top Overlay" at 10160.8,7669.68 h60
  text "2" at 9750.88,7549.68 h60
  text "Top Solder" at 10160.8,7549.68 h60
  text "Solder Resist" at 11100.54,7549.68 h60
  text "0.40mil" at 11960.3,7549.68 h60
  text "3.5" at 12610.14,7549.68 h60
  text "3" at 9750.88,7429.68 h60
  text "Top Layer" at 10160.8,7429.68 h60
  text "Copper" at 11100.54,7429.68 h60
  text "1.40mil" at 11960.3,7429.68 h60
  text "4" at 9750.88,7309.68 h60
  text "Dielectric 1" at 10160.8,7309.68 h60
  text "FR-4" at 11100.54,7309.68 h60
  text "15.00mil" at 11960.3,7309.68 h60
  text "4.2" at 12610.14,7309.68 h60
  text "5" at 9750.88,7189.68 h60
  text "Signal Layer 1" at 10160.8,7189.68 h60
  text "Copper" at 11100.54,7189.68 h60
  text "2.80mil" at 11960.3,7189.68 h60
  text "6" at 9750.88,7069.68 h60
  text "Dielectric 3" at 10160.8,7069.68 h60
  text "22.80mil" at 11960.3,7069.68 h60
  text "4.2" at 12610.14,7069.68 h60
  text "7" at 9750.88,6949.68 h60
  text "Signal Layer 2" at 10160.8,6949.68 h60
  text "Copper" at 11100.54,6949.68 h60
  text "2.80mil" at 11960.3,6949.68 h60
  text "8" at 9750.88,6829.68 h60
  text "Dielectric 2" at 10160.8,6829.68 h60
  text "FR-4" at 11100.54,6829.68 h60
  text "15.00mil" at 11960.3,6829.68 h60
  text "4.2" at 12610.14,6829.68 h60
  text "9" at 9750.88,6709.68 h60
  text "Bottom Layer" at 10160.8,6709.68 h60
  text "Copper" at 11100.54,6709.68 h60
  text "1.40mil" at 11960.3,6709.68 h60
  text "10" at 9750.88,6589.68 h60
  text "Bottom Solder" at 10160.8,6589.68 h60
  text "Solder Resist" at 11100.54,6589.68 h60
  text "0.40mil" at 11960.3,6589.68 h60
  text "3.5" at 12610.14,6589.68 h60
  text "11" at 9750.88,6469.68 h60
  text "Bottom Overlay" at 10160.8,6469.68 h60
Drill Drawing:
  circle w10: c6448.72,1071.96 r27.63
  lines w10: 6421.09,187.91 6434.9,187.91 6434.9,174.1 6462.53,174.1 6462.53,187.91 6476.34,187.91 6476.34,215.54 6462.53,215.54 6462.53,229.35 6434.9,229.35 6434.9,215.54 6421.09,215.54 6421.09,187.91 ; 6421.09,298.42 6448.72,312.23 6476.34,298.42 6462.53,326.04 6476.34,353.67 6448.72,339.86 6421.09,353.67 6434.9,326.04 6421.09,298.42 ; 6421.09,450.36 6448.72,422.74 6476.34,450.36 6448.72,477.99 6421.09,450.36 ; 6421.09,547.06 6421.09,560.87 6434.9,574.68 6421.09,588.5 6421.09,602.31 6434.9,602.31 6448.72,588.5 6462.53,602.31 6476.34,602.31 6476.34,588.5 6462.53,574.68 6476.34,560.87 6476.34,547.06 6462.53,547.06 6448.72,560.87 6434.9,547.06 6421.09,547.06 ; 6421.09,671.38 6476.34,671.38 6476.34,726.63 6421.09,726.63 6421.09,671.38 ; 6421.09,809.51 6434.9,809.51 6434.9,795.7 6462.53,795.7 6462.53,809.51 6476.34,809.51 6476.34,837.14 6462.53,837.14 6462.53,850.95 6434.9,850.95 6434.9,837.14 6421.09,837.14 6421.09,809.51 ; 6421.09,920.02 6476.34,920.02 6476.34,975.27 6421.09,975.27 6421.09,920.02 ; 6421.09,1182.47 6434.9,1182.47 6448.72,1168.66 6462.53,1182.47 6476.34,1182.47 6462.53,1196.28 6476.34,1210.1 6462.53,1210.1 6448.72,1223.91 6434.9,1210.1 6421.09,1210.1 6434.9,1196.28 6421.09,1182.47 ; 6432.14,815.03 6440.43,815.03 6440.43,806.75 6457.01,806.75 6457.01,815.03 6465.29,815.03 6465.29,831.61 6457.01,831.61 6457.01,839.9 6440.43,839.9 6440.43,831.61 6432.14,831.61 6432.14,815.03 ; 6432.14,931.07 6465.29,931.07 6465.29,964.22 6432.14,964.22 6432.14,931.07
  lines w12: 6371,136.8 9602.49,136.8 ; 6371,1255.68 9602.49,1255.68 ; 6708.86,12.48 6708.86,1380 ; 7040.86,12.48 7040.86,1380 ; 7677.43,12.48 7677.43,1380 ; 7936.57,12.48 7936.57,1380 ; 8311.72,12.48 8311.72,1380 ; 9036.05,12.48 9036.05,1380 ; 6371,12.48 9602.49,12.48 9602.49,1380 6371,1380 6371,12.48
  text "Symbol" at 6445.59,1292.98 h72
  text "Quantity" at 6746.16,1292.98 h72
  text "Finished Hole Size" at 7078.16,1292.98 h72
  text "Plated" at 7714.72,1292.98 h72
  text "Hole Type" at 7973.86,1292.98 h72
  text "Drill Layer Pair" at 8349.02,1292.98 h72
  text "Hole Tolerance" at 9073.35,1292.98 h72
  text "21" at 6746.16,1168.66 h60
  text "7.87mil (0.200mm)" at 7078.16,1168.66 h60
  text "PTH" at 7714.72,1168.66 h60
  text "Round" at 7973.86,1168.66 h60
  text "Top Layer - Bottom Layer" at 8349.02,1168.66 h60
  text "184" at 6746.16,1044.34 h60
  text "8.00mil (0.203mm)" at 7078.16,1044.34 h60
  text "PTH" at 7714.72,1044.34 h60
  text "Round" at 7973.86,1044.34 h60
  text "Top Layer - Bottom Layer" at 8349.02,1044.34 h60
  text "11" at 6746.16,920.02 h60
  text "12.00mil (0.305mm)" at 7078.16,920.02 h60
  text "PTH" at 7714.72,920.02 h60
  text "Round" at 7973.86,920.02 h60
  text "Top Layer - Bottom Layer" at 8349.02,920.02 h60
  text "50" at 6746.16,795.7 h60
  text "18.00mil (0.457mm)" at 7078.16,795.7 h60
  text "PTH" at 7714.72,795.7 h60
  text "Round" at 7973.86,795.7 h60
  text "Top Layer - Bottom Layer" at 8349.02,795.7 h60
  text "22" at 6746.16,671.38 h60
  text "31.89mil (0.810mm)" at 7078.16,671.38 h60
  text "PTH" at 7714.72,671.38 h60
  text "Round" at 7973.86,671.38 h60
  text "Top Layer - Bottom Layer" at 8349.02,671.38 h60
  text "+/-1.97mil" at 9073.35,671.38 h60
  text "8" at 6746.16,547.06 h60
  text "35.04mil (0.890mm)" at 7078.16,547.06 h60
  text "PTH" at 7714.72,547.06 h60
  text "Round" at 7973.86,547.06 h60
  text "Top Layer - Bottom Layer" at 8349.02,547.06 h60
  text "2" at 6746.16,422.74 h60
  text "51.18mil (1.300mm)" at 7078.16,422.74 h60
  text "PTH" at 7714.72,422.74 h60
  text "Round" at 7973.86,422.74 h60
  text "Top Layer - Bottom Layer" at 8349.02,422.74 h60
  text "2" at 6746.16,298.42 h60
  text "61.81mil (1.570mm)" at 7078.16,298.42 h60
  text "PTH" at 7714.72,298.42 h60
  text "Round" at 7973.86,298.42 h60
  text "Top Layer - Bottom Layer" at 8349.02,298.42 h60
  text "2" at 6746.16,174.1 h60
  text "128.00mil (3.251mm)" at 7078.16,174.1 h60
  text "PTH" at 7714.72,174.1 h60
  text "Round" at 7973.86,174.1 h60
  text "Top Layer - Bottom Layer" at 8349.02,174.1 h60
  text "302 Total" at 6746.16,49.78 h60

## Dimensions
0,-400 to 1000,-400 on M2 Board Dimensions
0,0 to 0,1060 on M2 Board Dimensions
0,0 to 6100,0 on M2 Board Dimensions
